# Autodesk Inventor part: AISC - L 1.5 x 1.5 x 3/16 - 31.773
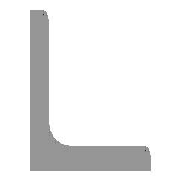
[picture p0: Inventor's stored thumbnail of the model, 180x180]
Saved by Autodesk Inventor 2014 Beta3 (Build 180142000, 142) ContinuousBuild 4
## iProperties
_CCFamilyMember: 5
_CCFamilyDisplayName: ANSI L (Equal angles) - Angle Steel
_FrameMemberDoc: Frame Member File
_Version: 15.0.0
_GetPNFromCC: 1
Created: 2010-11
Part Number: AISC - L 1.5 x 1.5 x 3/16 - 31.773
Material: Steel, Mild
Description: Angle Steel
Document SubType Name: Modeling
Standard: ANSI
Designer: Beta-8540w
Standards Organization: ANSI
Language: en-US
Size Designation: L 1.5 x 1.5 x 3/16
Categories: <MemberInstance><Categories><Category DisplayName="Structural Shapes" InternalName="089c4875-fa83-4c05-b084-43b9cc11f5ed" Mnemonic="GRDR"><CategoryParameter Dis
Stock Number: L 1.5 x 1.5 x 3/16
Density: 7.86 g/cm^3
Appearance: Steel
IsCustomPart: 1
G_L: 31.773 in
G_W: 1.500 in
G_H: 1.500 in
+D492D07F-02B9-496C-B776-82EB711B3C50+CUTDETAIL1: Cut
Author: Beta-8540w
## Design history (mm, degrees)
node "Start plane"
node "End plane"
sketch "Sketch"
  geometry: L1 (38.1, 0)-(0, 0); L2 (0, 0)-(0, 38.1); L3 (0, 38.1)-(2.476, 38.1); L4 (4.762, 35.814)-(4.762, 9.589); L5 (9.588, 4.763)-(35.814, 4.763); L6 (38.1, 2.477)-(38.1, 0); L7 (0, -11.041)-(0, 31.538); L8 (-11.041, 0)-(31.538, 0); L9 (0, 48.496)-(0, -20.964) reference; L10 (-20.964, 0)-(48.496, 0) reference; A1 r 4.826 centre (9.588, 9.589) between (4.762, 9.589) and (9.588, 4.763); A2 r 2.286 centre (2.476, 35.814) between (4.762, 35.814) and (2.476, 38.1); A3 r 2.286 centre (35.814, 2.477) between (38.1, 2.477) and (35.814, 4.763); 3 further points
  constraints: 16 end point, 6 point on circle, 6 point on line, 6 tangent, 4 parallel, 3 centre point, 2 collinear, 1 equal radius, 1 horizontal, 1 perpendicular
  dimensions: "d0" = 38.1 distance between parallel lines of L6 L2 (= G_H); "d1" = 38.1 distance between parallel lines of L3 L1 (= G_H); "d2" = 4.7625 distance between parallel lines of L2 L4 (= G_T); "d3" = 4.7625 distance between parallel lines of L1 L5 (= G_T); "d10" = 0 distance between parallel lines of L7 L2 (computed from ex); "d11" = 0 distance between parallel lines of L8 L1 (computed from d10); "d14" = 4.826 radius of A1 (= G_IR); "d15" = 2.286 radius of A2 (= G_ER)
extrude "Body" new body sketch "Sketch" stored distance "d4" = 807.03543 (= G_L); taper "d5" = 0 deg
node "Driven Length"
  sketch "Sketch3"
    geometry: L1 (0, 0)-(10, 0) reference
    constraints: 2 end point, 1 horizontal
  workplane "Work Plane3"
  sketch "Sketch4"
    geometry: L1 (-2, 0)-(12, 0) reference; L2 (-2, 807.035)-(12, 807.035) reference
    dimensions: "d17" = 807.03543 distance between parallel lines of L1 L2 (derived)
workplane "Work Plane4"
split "Split1"
body "Solid1"
other parameters: "G_H" = 38.1 [user parameter; used in 2 equation terms], "G_T" = 4.7625 [user parameter; used in 2 equation terms], "G_ER" = 2.286 [user parameter; used in 1 equation term], "G_IR" = 4.826 [user parameter; used in 1 equation term], "G_L" = 807.03543 (= d17) [user parameter; used in 1 equation term], "ex" = 0 [user parameter; used in 1 equation term], "G_OFFSET_START" = 0 [user parameter; used in 1 equation term], "G_OFFSET_END" = -29.72999 [user parameter; used in 1 equation term], "d12" = 0 (computed from G_OFFSET_START), "d13" = 807.03543 (= G_OFFSET_END + B_L), "B_L" = 836.76542 [user parameter; used in 1 equation term], "d16" = 90 deg, "MAS" = 0.26787 [user parameter]
